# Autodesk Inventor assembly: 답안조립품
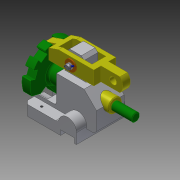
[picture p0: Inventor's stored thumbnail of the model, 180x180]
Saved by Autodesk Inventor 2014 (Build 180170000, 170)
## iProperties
Created: 2016-11
Part Number: 답안조립품
Document SubType Name: Assembly
Designer: USER
Author: USER
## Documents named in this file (8)
- C:\Users\USER\Desktop\461107V1011\답안조립품.iam
- C:\Users\USER\Desktop\461107V1011\본체.ipt
- C:\Users\USER\Desktop\461107V1011\부시.ipt
- C:\Users\USER\Desktop\461107V1011\분할대.ipt
- C:\Users\USER\Desktop\461107V1011\분할축.ipt
- C:\Users\USER\Desktop\461107V1011\와셔.ipt
- C:\Users\USER\Desktop\461107V1011\원통형핀.ipt
- C:\Users\USER\Desktop\461107V1011\클레비스핀.ipt
